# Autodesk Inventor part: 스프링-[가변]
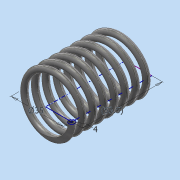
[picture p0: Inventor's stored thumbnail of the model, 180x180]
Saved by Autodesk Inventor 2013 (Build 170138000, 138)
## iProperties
Created: 2014-12
Part Number: 스프링-[가변]
Material: 강철, 탄소
Document SubType Name: Modeling
Designer: WINDOWS7
Mass: 80.2781 g
Surface Area: 103.293 cm^2
Volume: 10.2005 cm^3
Density: 7.87 g/cm^3
Author: WINDOWS7
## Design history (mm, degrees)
sketch "스케치1"
  geometry: L1 (0, 0)-(17.5, 0); L2 (17.5, 0)-(17.5, 48.5); L3 (17.5, 48.5)-(0, 48.5); L4 (0, 48.5)-(0, 0); C1 r 2 at (17.5, 0)
  constraints: 8 end point, 2 parallel, 1 centre point, 1 coincident, 1 horizontal, 1 perpendicular
  dimensions: "d0" = 35 diameter of L2 L4; "d2" = 48.5 distance of L1.end L2.end (derived); "d3" = 4 diameter of C1
feature "코일1" sketch "스케치1" pitch "d4" = 10; turns "d6" = 7.5; dims "d5" = 48.5 (= d2), "d7" = 0, angle "d8" = 90 deg, angle "d9" = 90 deg, "d10" = 0, "d11" = 0
sketch "스케치2"
  geometry: L1 (-19.5, 0)-(-15.5, 0) reference; 1 further point
  constraints: 1 horizontal alignment
extrude "돌출1" cut sketch "스케치2" distance "d12" = 10; taper "d13" = 0 deg
node "작업 평면1"
sketch "스케치3"
  geometry: L1 (-4, 0)-(0, 0) reference; 1 further point
  constraints: 1 horizontal alignment
extrude "돌출2" cut sketch "스케치3" distance "d14" = 10; taper "d15" = 0 deg
node "솔리드1"
node "절단 모서리 투영1"
node "절단 모서리 투영2"
